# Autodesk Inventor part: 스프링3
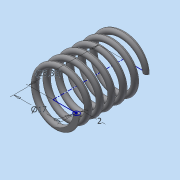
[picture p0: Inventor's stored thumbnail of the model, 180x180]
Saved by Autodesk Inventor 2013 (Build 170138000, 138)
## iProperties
Created: 2019-07
Part Number: 스프링3
Material: 일반
Document SubType Name: Modeling
Designer: dgall
Density: 1 g/cm^3
Mass: -0.0170894 g
Surface Area: 20.0756 cm^2
Volume: -0.0170894 cm^3
Author: dgall
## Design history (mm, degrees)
sketch "스케치1"
  geometry: L1 (8.5, 0)-(0, 0); L2 (0, 0)-(0, 25.33); L3 (0, 25.33)-(8.5, 25.33); C1 r 1 at (8.5, 0)
  constraints: 6 end point, 2 parallel, 1 centre point, 1 coincident, 1 horizontal, 1 perpendicular
  dimensions: "d0" = 17 diameter of L1.start L2; "d2" = 25.33013 distance of L1.end L2.end (derived); "d3" = 2 diameter of C1
feature "코일1" pitch "d4" = 10; turns "d6" = 6; dims "d5" = 25.33013 (= d2), "d7" = 0, angle "d8" = 90 deg, angle "d9" = 90 deg, "d10" = 0, "d11" = 0
node "작업 평면1"
feature "분할1"
feature "분할2"
node "솔리드1"
